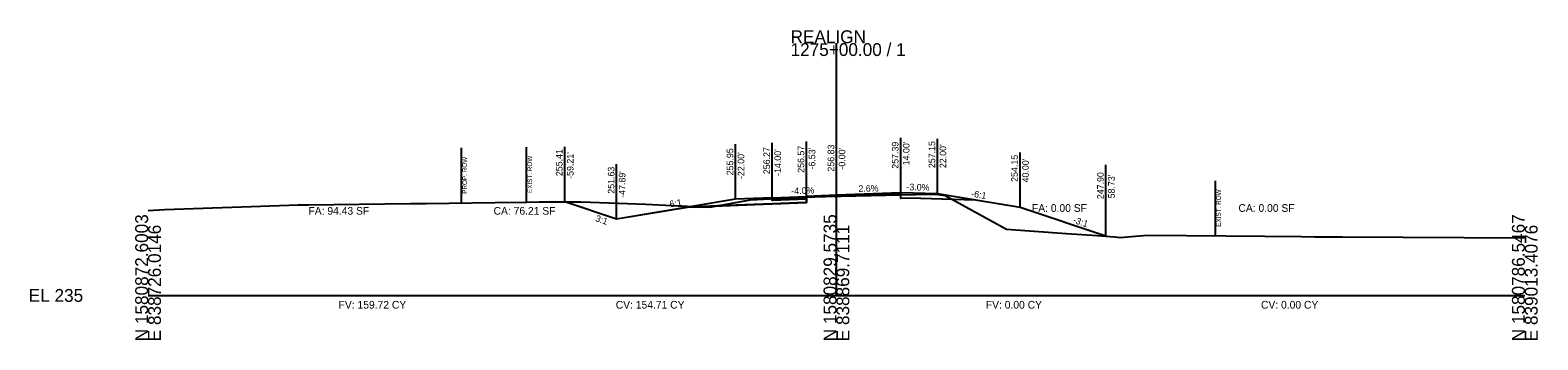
# Model space of a CAD drawing. Extents: x -26 to 6303, y -16 to 9563.
# Drawn here: x 4974.3 to 5302.8, y 8490.3 to 8557.8 of the extents above; entities that cross this region are included whole.
import ezdxf

# ---------------------------------------------------------------- set-up
doc = ezdxf.new("R2010")
doc.units = 0
for name, color, linetype in [('ASPHALT_19MM1', 7, 'Continuous'), ('ASPHALT_9_5MM1', 7, 'Continuous'), ('Default', 7, 'Continuous'), ('Draft_XS_Grid', 7, 'Continuous'), ('DTM_TEMP_DROP', 7, 'Continuous'), ('DTM_X_GROUND', 7, 'Continuous'), ('X_TRANS_EOP', 7, 'Continuous'), ('XS_CELL', 7, 'Continuous'), ('XS_M_SHAPES_EARTHWORK', 7, 'Continuous'), ('XS_P_ASPHALT', 7, 'Continuous'), ('XS_P_GROUND', 7, 'Continuous'), ('XS_P_ROW', 7, 'Continuous'), ('XS_P_SHOULDER', 7, 'Continuous'), ('XS_P_SUBGRADE_GRANULAR', 7, 'Continuous'), ('XS_P_SUBGRADE_LEVELING', 7, 'Continuous'), ('XS_P_SUBGRADE_MILLING', 7, 'Continuous'), ('XS_P_TX_CLEARZONE', 7, 'Continuous'), ('XS_P_TX_FS_BS', 7, 'Continuous'), ('XS_SHEET_EW_TX_AREA', 7, 'Continuous'), ('XS_SHEET_EW_TX_VOLUME', 7, 'Continuous'), ('XS_X_ROW', 7, 'Continuous')]:
    doc.layers.add(name, color=color, linetype=linetype)

msp = doc.modelspace()

# ---------------------------------------------------------------- linework, layer by layer
at = {"layer": 'ASPHALT_19MM1'}
msp.add_lwpolyline([(5143.47, 8521.23), (5143.47, 8520.96), (5136, 8520.66), (5136, 8520.93), (5143.47, 8521.23)], dxfattribs=at)
at = {"layer": 'ASPHALT_9_5MM1'}
msp.add_lwpolyline([(5143.47, 8521.57), (5143.47, 8521.44), (5136, 8521.14), (5136, 8521.27), (5143.47, 8521.57)], dxfattribs=at)
at = {"layer": 'Default'}
msp.add_lwpolyline([(5143.47, 8521.44), (5143.47, 8521.23), (5136, 8520.93), (5136, 8521.14), (5143.47, 8521.44)], dxfattribs=at)
at = {"layer": 'DTM_X_GROUND'}
msp.add_lwpolyline([(5000, 8518.54), (5003.59, 8518.71), (5022.44, 8519.38), (5032.68, 8519.72), (5033.57, 8519.75), (5034.05, 8519.76), (5034.89, 8519.76), (5057.19, 8520.02), (5060.61, 8520.07), (5075.62, 8520.26), (5082.51, 8520.35), (5085.19, 8520.37), (5094.34, 8520.43), (5108.48, 8519.86), (5114.24, 8519.59), (5122.39, 8519.21), (5125.64, 8519.81), (5131.25, 8520.85), (5135.54, 8521.06), (5139.81, 8521.28), (5142.68, 8521.43), (5143.47, 8521.47), (5150.94, 8521.65), (5157.52, 8521.81), (5170.74, 8522.09), (5171.42, 8522.11), (5171.58, 8522.09), (5173.67, 8521.81), (5179.63, 8518.52), (5187.09, 8514.42), (5200.15, 8513.51), (5206.83, 8513.06), (5210.58, 8512.75), (5211.91, 8512.64), (5213.44, 8512.76), (5217.78, 8513.1), (5243.32, 8512.89), (5251.33, 8512.83), (5254.28, 8512.8), (5260.3, 8512.77), (5300, 8512.55)], dxfattribs=at)
at = {"layer": 'XS_CELL'}
for p, q in [((5150, 8500), (5150, 8555)), ((5000, 8500), (5150, 8500)), ((5150, 8500), (5300, 8500))]:
    msp.add_line(p, q, dxfattribs=at)
at = {"layer": 'XS_M_SHAPES_EARTHWORK'}
for points in [[(5090.79, 8520.41), (5094.34, 8520.43), (5108.48, 8519.86), (5114.24, 8519.59), (5119.57, 8519.34), (5117.97, 8519.27), (5102.11, 8516.63)], [(5119.57, 8519.34), (5122.39, 8519.21), (5124.06, 8519.52)], [(5124.06, 8519.52), (5125.64, 8519.81), (5131.25, 8520.85), (5135.54, 8521.06), (5139.81, 8521.28), (5142.68, 8521.43), (5143.47, 8521.47), (5145.3, 8521.51), (5143.47, 8521.44), (5143.47, 8521.23), (5143.47, 8520.96), (5143.47, 8520.29), (5136, 8520), (5134, 8519.92)], [(5164, 8521.95), (5170.74, 8522.09), (5171.42, 8522.11), (5171.58, 8522.09), (5173.67, 8521.81), (5175.28, 8520.92), (5166, 8521.2), (5164, 8521.12)], [(5175.28, 8520.92), (5179.63, 8518.52), (5187.09, 8514.42), (5200.15, 8513.51), (5206.83, 8513.06), (5208.73, 8512.9), (5190, 8519.15), (5180.27, 8520.77)]]:
    msp.add_lwpolyline(points, close=True, dxfattribs=at)
at = {"layer": 'XS_P_ASPHALT'}
msp.add_lwpolyline([(5143.47, 8521.44), (5143.47, 8521.44), (5150, 8521.7), (5164, 8522.26), (5164, 8522.26), (5164, 8522.39), (5164, 8522.39), (5150, 8521.83), (5143.47, 8521.57), (5143.47, 8521.57), (5143.47, 8521.44)], dxfattribs=at)
at = {"layer": 'XS_P_GROUND'}
for points in [[(5208.73, 8512.9), (5208.73, 8512.9), (5190, 8519.15), (5172, 8522.15), (5172, 8522.15)], [(5128, 8520.95), (5102.11, 8516.63), (5090.79, 8520.41)]]:
    msp.add_lwpolyline(points, dxfattribs=at)
at = {"layer": 'XS_P_ROW'}
msp.add_line((5068.29, 8520.16), (5068.29, 8532.16), dxfattribs=at)
at = {"layer": 'XS_P_SHOULDER'}
for points in [[(5172, 8522.15), (5164, 8522.39), (5164, 8522.39)], [(5136, 8521.27), (5128, 8520.95)]]:
    msp.add_lwpolyline(points, dxfattribs=at)
at = {"layer": 'XS_P_SUBGRADE_GRANULAR'}
for points in [[(5164, 8521.12), (5164, 8522.39)], [(5117.97, 8519.27), (5134, 8519.92), (5134, 8519.92), (5136, 8520), (5136, 8520)], [(5136, 8520), (5136, 8520), (5143.47, 8520.29)], [(5143.47, 8520.29), (5143.47, 8521.57)], [(5180.27, 8520.77), (5166, 8521.2), (5166, 8521.2), (5166, 8521.2), (5164, 8521.12)]]:
    msp.add_lwpolyline(points, dxfattribs=at)
at = {"layer": 'XS_P_SUBGRADE_LEVELING'}
msp.add_lwpolyline([(5143.47, 8521.44), (5143.47, 8521.44), (5145.3, 8521.51), (5150, 8521.63), (5150, 8521.63), (5150.94, 8521.65), (5150.94, 8521.65), (5157.52, 8521.81), (5157.52, 8521.81), (5157.52, 8521.81), (5164, 8521.95), (5164, 8521.95), (5164, 8522.26), (5164, 8522.26), (5164, 8522.26), (5157.52, 8522), (5157.52, 8522), (5157.52, 8522), (5150.94, 8521.74), (5150.94, 8521.74), (5150, 8521.7), (5143.47, 8521.44), (5143.47, 8521.44)], dxfattribs=at)
at = {"layer": 'XS_P_SUBGRADE_MILLING'}
msp.add_lwpolyline([(5164, 8521.95), (5164, 8521.95), (5157.52, 8521.81), (5157.52, 8521.81), (5157.52, 8521.81), (5150.94, 8521.65), (5150.94, 8521.65), (5150, 8521.63), (5143.47, 8521.47), (5143.47, 8521.47), (5143.47, 8521.44), (5143.47, 8521.44), (5145.3, 8521.51), (5150, 8521.63), (5150, 8521.63), (5150.94, 8521.65), (5150.94, 8521.65), (5157.52, 8521.81), (5157.52, 8521.81), (5157.52, 8521.81), (5164, 8521.95), (5164, 8521.95)], dxfattribs=at)
at = {"layer": 'XS_P_TX_CLEARZONE'}
for p, q in [((5090.79, 8520.41), (5090.79, 8532.41)), ((5128, 8520.95), (5128, 8532.95)), ((5136, 8521.27), (5136, 8533.27)), ((5143.47, 8521.57), (5143.47, 8533.57)), ((5150, 8521.83), (5150, 8533.83)), ((5164, 8522.39), (5164, 8534.39)), ((5172, 8522.15), (5172, 8534.15)), ((5190, 8519.15), (5190, 8531.15)), ((5102.11, 8516.63), (5102.11, 8528.63)), ((5208.73, 8512.9), (5208.73, 8528.47))]:
    msp.add_line(p, q, dxfattribs=at)
at = {"layer": 'XS_X_ROW'}
for p, q in [((5082.49, 8520.34), (5082.49, 8532.34)), ((5232.57, 8512.98), (5232.57, 8524.98))]:
    msp.add_line(p, q, dxfattribs=at)

# ---------------------------------------------------------------- texts
at = {"layer": 'Draft_XS_Grid'}
msp.add_text('-', height=0.0001, dxfattribs=at).set_placement((5000, 8500))
at = {"layer": 'DTM_TEMP_DROP'}
for p in [(5163.92, 8522.27), (5135.92, 8521.15), (5143.4, 8521.45), (5149.92, 8521.71)]:
    msp.add_text('X', height=0.24, dxfattribs=at).set_placement(p)
at = {"layer": 'X_TRANS_EOP'}
for p in [(5090.71, 8520.29), (5208.66, 8512.78)]:
    msp.add_text('X', height=0.24, dxfattribs=at).set_placement(p)
at = {"layer": 'XS_CELL'}
for s, p in [('1275+00.00 / 1', (5140, 8552.2)), ('REALIGN', (5140, 8555)), ('EL 235', (4974, 8498.6))]:
    msp.add_text(s, height=2.8, dxfattribs=at).set_placement(p)
for s, p in [('N 1580872.6003', (5000, 8490)), ('N 1580829.5735', (5150, 8490)), ('N 1580786.5467', (5300, 8490)), ('E 838726.0146', (5002.8, 8490)), ('E 838869.7111', (5152.8, 8490)), ('E 839013.4076', (5302.8, 8490))]:
    msp.add_text(s, height=2.8, rotation=90, dxfattribs=at).set_placement(p)
at = {"layer": 'XS_P_ASPHALT'}
msp.add_text('X', height=0.24, dxfattribs=at).set_placement((5189.92, 8519.03))
at = {"layer": 'XS_P_ROW'}
msp.add_text('PROP. ROW', height=1, rotation=90, dxfattribs=at).set_placement((5069.49, 8522.16))
at = {"layer": 'XS_P_SHOULDER'}
for p in [(5171.92, 8522.03), (5127.92, 8520.83)]:
    msp.add_text('X', height=0.24, dxfattribs=at).set_placement(p)
at = {"layer": 'XS_P_SUBGRADE_GRANULAR'}
for p in [(5102.03, 8516.51), (5208.66, 8512.78)]:
    msp.add_text('X', height=0.24, dxfattribs=at).set_placement(p)
at = {"layer": 'XS_P_TX_CLEARZONE'}
for s, p in [('255.95', (5127.52, 8526.19)), ('256.27', (5135.52, 8526.44)), ('256.57', (5142.99, 8526.74)), ("-6.53'", (5145.39, 8527.45)), ('256.83', (5149.52, 8527)), ("-0.00'", (5151.92, 8527.44)), ('257.39', (5163.52, 8527.62)), ("14.00'", (5165.92, 8528.36)), ('257.15', (5171.52, 8527.76)), ("22.00'", (5173.92, 8527.76)), ('255.41', (5090.31, 8526.01)), ("-59.21'", (5092.71, 8525.42)), ("-22.00'", (5129.92, 8525.38)), ("-14.00'", (5137.92, 8526.06)), ('254.15', (5189.52, 8524.76)), ("40.00'", (5191.92, 8524.64)), ('251.63', (5101.63, 8522.17)), ("-47.89'", (5104.03, 8521.29)), ('247.90', (5208.25, 8520.99)), ("58.73'", (5210.65, 8521.16))]:
    msp.add_text(s, height=1.44, rotation=90, dxfattribs=at).set_placement(p)
at = {"layer": 'XS_P_TX_FS_BS'}
for s, rotation, p in [('-4.0%', 2.2906, (5140.18, 8522.03)), ('2.6%', 1.4659, (5154.8, 8522.55)), ('-3.0%', 358.2816, (5165.23, 8522.95)), ('-6:1', 350.5377, (5179.28, 8521.54)), ('-6:1', 9.4642, (5113.13, 8519.08)), ('3:1', 341.5668, (5097.35, 8516.21)), ('-3:1', 341.5651, (5201.42, 8515.87))]:
    msp.add_text(s, height=1.44, rotation=rotation, dxfattribs=at).set_placement(p)
at = {"layer": 'XS_SHEET_EW_TX_AREA'}
for s, p in [('FA: 94.43 SF', (5034.95, 8517.6)), ('CA: 76.21 SF', (5075.29, 8517.6)), ('FA: 0.00 SF', (5192.6, 8518.22)), ('CA: 0.00 SF', (5237.6, 8518.22))]:
    msp.add_text(s, height=1.68, dxfattribs=at).set_placement(p)
at = {"layer": 'XS_SHEET_EW_TX_VOLUME'}
for s, p in [('FV: 159.72 CY', (5041.52, 8497.12)), ('CV: 154.71 CY', (5101.91, 8497.12)), ('FV: 0.00 CY', (5182.55, 8497.12)), ('CV: 0.00 CY', (5242.51, 8497.12))]:
    msp.add_text(s, height=1.68, dxfattribs=at).set_placement(p)
at = {"layer": 'XS_X_ROW'}
for p in [(5083.69, 8522.34), (5233.77, 8514.98)]:
    msp.add_text('EXIST. ROW', height=1, rotation=90, dxfattribs=at).set_placement(p)

doc.saveas('drawing.dxf')
